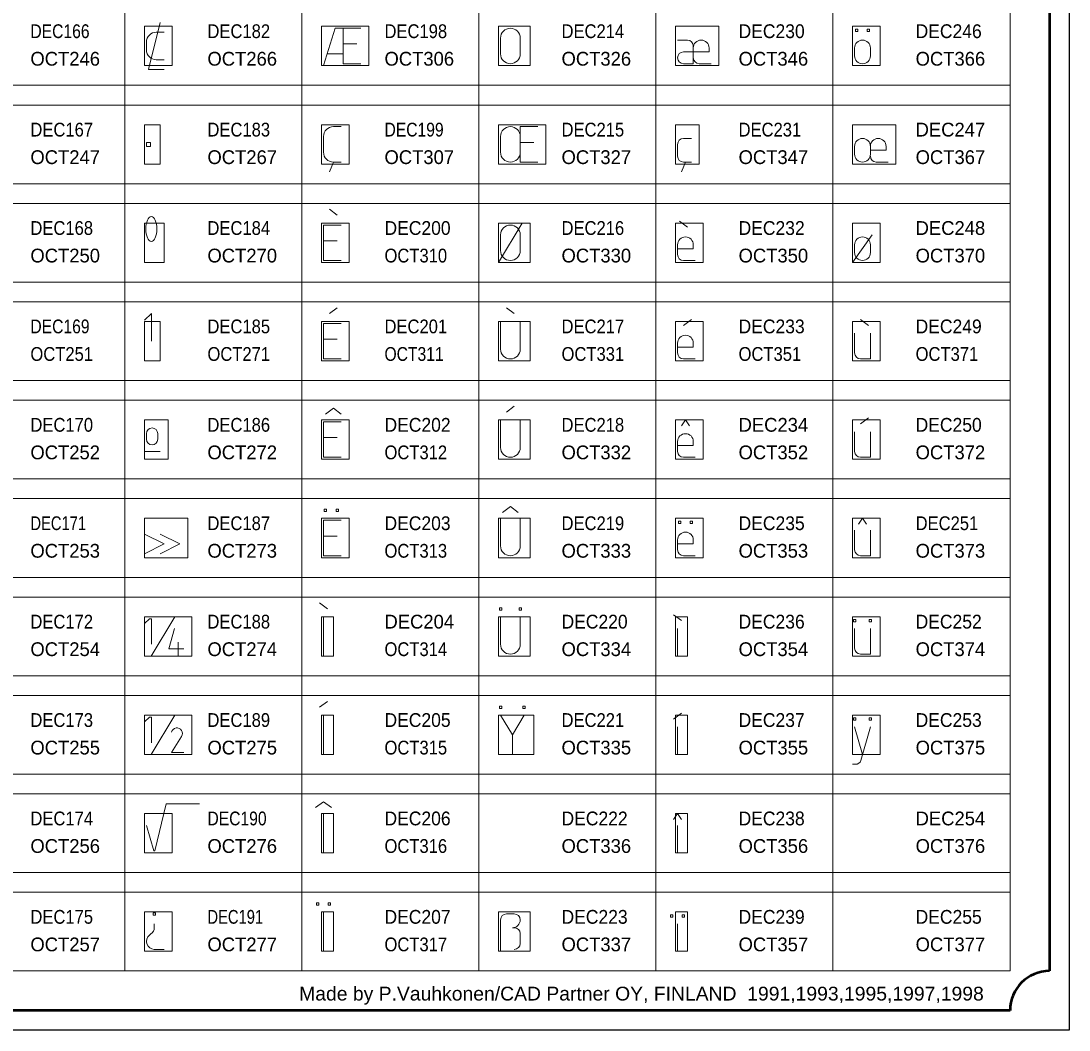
# Model space of a CAD drawing. Extents: x -200 to 7300, y -200 to 4800.
# Drawn here: x 4636 to 7300, y -200 to 2364 of the extents above; entities that cross this region are included whole.
import ezdxf
from ezdxf.enums import TextEntityAlignment as Align

# ---------------------------------------------------------------- set-up
doc = ezdxf.new("R2010")
doc.units = 0
doc.header["$LTSCALE"] = 14
for name, color, linetype, lineweight in [('1', 7, 'Continuous', 13), ('5', 7, 'Continuous', 40), ('6', 7, 'Continuous', 13), ('63', 7, 'Continuous', 13)]:
    doc.layers.add(name, color=color, linetype=linetype, lineweight=lineweight)
doc.layers.add('10', color=7, linetype='Continuous')
doc.layers.add('11', color=7, linetype='Continuous')

msp = doc.modelspace()

# ---------------------------------------------------------------- linework, layer by layer
at = {"layer": '1'}
for p, q in [((5000, 2335), (4980, 2335)), ((5855, 2320), (5855, 2280)), ((5905, 2320), (5905, 2280)), ((4955, 2310), (4955, 2290)), ((5490, 2305), (5455, 2305)), ((6305, 2315), (6330, 2315)), ((6755, 2295), (6755, 2275)), ((6795, 2295), (6795, 2275)), ((4980, 2265), (5000, 2265)), ((5414, 2280), (5455, 2280)), ((6390, 2255), (6360, 2255)), ((5450, 2095), (5430, 2095)), ((5405, 2070), (5405, 2030)), ((5855, 2070), (5855, 2030)), ((5940, 2055), (5905, 2055)), ((6340, 2065), (6320, 2065)), ((6305, 2050), (6305, 2020)), ((6755, 2045), (6755, 2025)), ((6795, 2045), (6795, 2025)), ((5430, 2005), (5420, 1980)), ((5430, 2005), (5450, 2005)), ((6325, 2005), (6315, 1980)), ((6320, 2005), (6340, 2005)), ((6840, 2005), (6810, 2005)), ((5440, 1870), (5420, 1885)), ((5850, 1750), (5910, 1850)), ((6330, 1840), (6310, 1855)), ((5855, 1820), (5855, 1780)), ((5905, 1820), (5905, 1780)), ((6800, 1820), (6750, 1750)), ((5440, 1805), (5405, 1805)), ((6305, 1770), (6305, 1795)), ((6755, 1795), (6755, 1775)), ((6795, 1795), (6795, 1775)), ((6350, 1755), (6320, 1755)), ((5420, 1620), (5440, 1635)), ((5890, 1620), (5870, 1635)), ((5855, 1600), (5855, 1530)), ((5905, 1600), (5905, 1530)), ((6320, 1590), (6340, 1605)), ((6790, 1590), (6770, 1605)), ((5440, 1555), (5405, 1555)), ((6755, 1570), (6755, 1520)), ((6305, 1520), (6305, 1545)), ((6350, 1505), (6320, 1505)), ((5870, 1370), (5890, 1385)), ((5855, 1350), (5855, 1280)), ((5905, 1350), (5905, 1280)), ((6770, 1340), (6790, 1355)), ((4955, 1315.4), (4955, 1301.1)), ((4983.6, 1315.4), (4983.6, 1301.1)), ((6755, 1320), (6755, 1270)), ((5440, 1305), (5405, 1305)), ((6305, 1270), (6305, 1295)), ((4950, 1270), (4990, 1270)), ((6350, 1255), (6320, 1255)), ((5855, 1100), (5855, 1030)), ((5905, 1100), (5905, 1030)), ((6755, 1070), (6755, 1020)), ((5440, 1055), (5405, 1055)), ((6305, 1020), (6305, 1045)), ((6350, 1005), (6320, 1005)), ((5415, 870), (5395, 885)), ((6315, 840), (6295, 855)), ((4967, 750), (5027, 850)), ((5405, 850), (5405, 750)), ((5855, 850), (5855, 780)), ((5905, 850), (5905, 780)), ((6305, 750), (6305, 820)), ((6755, 820), (6755, 770)), ((5036, 750), (5036, 785)), ((5395, 620), (5415, 635)), ((4967, 500), (5027, 600)), ((5405, 600), (5405, 500)), ((6295, 590), (6315, 605)), ((6305, 500), (6305, 570)), ((6755, 570), (6775, 500)), ((6795, 570), (6771, 485)), ((5885, 550), (5885, 500)), ((6757, 475), (6750, 475)), ((5405, 350), (5405, 250)), ((6305, 250), (6305, 320)), ((5405, 100), (5405, 0)), ((5855, 0), (5855, 80)), ((5870, 95), (5890, 95)), ((4975, 70), (4975, 61)), ((5885, 60), (5890, 60)), ((6305, 0), (6305, 70)), ((4966, 44), (4963, 41)), ((5905, 45), (5905, 20)), ((5000, 5), (4975, 5))]:
    msp.add_line(p, q, dxfattribs=at)
for points in [[(4990, 2360), (4960, 2240), (5000, 2240)], [(5405, 2250), (5435, 2345), (5500, 2345)], [(5455, 2345), (5455, 2255), (5500, 2255)], [(6345, 2300), (6345, 2255), (6320, 2255)], [(6320, 2285), (6385, 2285), (6385, 2295)], [(5950, 2095), (5905, 2095), (5905, 2005), (5950, 2005)], [(6795, 2035), (6835, 2035), (6835, 2045)], [(5450, 1845), (5405, 1845), (5405, 1755), (5450, 1755)], [(6305, 1785), (6345, 1785), (6345, 1795)], [(4968, 1550), (4968, 1620), (4950, 1603)], [(5450, 1595), (5405, 1595), (5405, 1505), (5450, 1505)], [(6770, 1505), (6795, 1505), (6795, 1570)], [(6305, 1535), (6345, 1535), (6345, 1545)], [(5450, 1365), (5430, 1380), (5410, 1365)], [(5450, 1345), (5405, 1345), (5405, 1255), (5450, 1255)], [(6335, 1335), (6325, 1350), (6315, 1335)], [(6770, 1255), (6795, 1255), (6795, 1320)], [(6305, 1285), (6345, 1285), (6345, 1295)], [(5900, 1115), (5880, 1130), (5860, 1115)], [(5450, 1095), (5405, 1095), (5405, 1005), (5450, 1005)], [(6785, 1085), (6775, 1100), (6765, 1085)], [(6770, 1005), (6795, 1005), (6795, 1070)], [(4950, 1060), (5000, 1035), (4950, 1010)], [(4990, 1060), (5040, 1035), (4990, 1010)], [(6305, 1035), (6345, 1035), (6345, 1045)], [(4968, 780), (4968, 845), (4963, 845), (4950, 833)], [(5050, 768), (5012, 768), (5026, 820)], [(6770, 755), (6795, 755), (6795, 820)], [(4968, 530), (4968, 595), (4963, 595), (4950, 583)], [(5855, 600), (5885, 550), (5915, 600)], [(5050, 505), (5019, 505), (5044.3, 545.9)], [(4955, 320), (4974, 255), (4976, 255), (5005, 375), (5090, 375)], [(5425, 365), (5405, 380), (5385, 365)], [(6315, 335), (6305, 350), (6295, 335)]]:
    msp.add_lwpolyline(points, dxfattribs=at)
for points in [[(6757, 2337), (6763, 2337), (6763, 2343), (6757, 2343)], [(6787, 2337), (6793, 2337), (6793, 2343), (6787, 2343)], [(4955, 2045), (4965, 2045), (4965, 2055), (4955, 2055)], [(5407, 1117), (5413, 1117), (5413, 1123), (5407, 1123)], [(5437, 1117), (5443, 1117), (5443, 1123), (5437, 1123)], [(6307, 1087), (6313, 1087), (6313, 1093), (6307, 1093)], [(6337, 1087), (6343, 1087), (6343, 1093), (6337, 1093)], [(5852, 867), (5858, 867), (5858, 873), (5852, 873)], [(5902, 867), (5908, 867), (5908, 873), (5902, 873)], [(6752, 837), (6758, 837), (6758, 843), (6752, 843)], [(6792, 837), (6798, 837), (6798, 843), (6792, 843)], [(5852, 617), (5858, 617), (5858, 623), (5852, 623)], [(5912, 617), (5918, 617), (5918, 623), (5912, 623)], [(6752, 587), (6758, 587), (6758, 593), (6752, 593)], [(6792, 587), (6798, 587), (6798, 593), (6792, 593)], [(5387, 117), (5393, 117), (5393, 123), (5387, 123)], [(5417, 117), (5423, 117), (5423, 123), (5417, 123)], [(4972, 92), (4978, 92), (4978, 98), (4972, 98)], [(6287, 87), (6293, 87), (6293, 93), (6287, 93)], [(6317, 87), (6323, 87), (6323, 93), (6317, 93)]]:
    msp.add_lwpolyline(points, close=True, dxfattribs=at)
for centre, radius, start, end in [((5880, 2320), 25, 0, 180), ((4980, 2310), 25, 90, 180), ((6330, 2300), 15, 0, 90), ((6365, 2295), 20, 0, 180), ((6775, 2295), 20, 0, 180), ((4980, 2290), 25, 180, 270), ((5880, 2280), 25, 180, 360), ((6320, 2270), 15, 90, 270), ((6360, 2270), 15, 180, 270), ((6775, 2275), 20, 180, 360), ((5430, 2070), 25, 90, 180), ((5880, 2070), 25, 0, 180), ((6320, 2050), 15, 90, 180), ((6775, 2045), 20, 0, 180), ((6815, 2045), 20, 0, 180), ((5430, 2030), 25, 180, 270), ((5880, 2030), 25, 180, 360), ((6775, 2025), 20, 180, 360), ((6320, 2020), 15, 180, 270), ((6810, 2020), 15, 180, 270), ((5880, 1820), 25, 0, 180), ((6325, 1795), 20, 0, 180), ((6775, 1795), 20, 0, 180), ((5880, 1780), 25, 180, 360), ((6320, 1770), 15, 180, 270), ((6775, 1775), 20, 180, 360), ((6325, 1545), 20, 0, 180), ((5880, 1530), 25, 180, 360), ((6320, 1520), 15, 180, 270), ((6770, 1520), 15, 180, 270), ((4969.3, 1315.4), 14.3, 0, 180), ((6325, 1295), 20, 0, 180), ((4969.3, 1301.1), 14.3, 180, 360), ((5880, 1280), 25, 180, 360), ((6320, 1270), 15, 180, 270), ((6770, 1270), 15, 180, 270), ((6325, 1045), 20, 0, 180), ((5880, 1030), 25, 180, 360), ((6320, 1020), 15, 180, 270), ((6770, 1020), 15, 180, 270), ((5880, 780), 25, 180, 360), ((6770, 770), 15, 180, 270), ((5032.5, 553.5), 14, 327.0948, 165.9638), ((6757.1, 490), 15, 270, 338.5769), ((5870, 80), 15, 90, 180), ((5885, 80), 20, 270, 360), ((5890, 80), 15, 0, 90), ((4955, 60.7), 20, 303.6901, 360), ((5890, 45), 15, 0, 90), ((4975, 25), 20, 126.8699, 270), ((5890, 20), 15, 270, 0)]:
    msp.add_arc(centre, radius, start, end, dxfattribs=at)
msp.add_ellipse((4967.5, 1835), major_axis=(0, -31.5), ratio=0.444444, dxfattribs=at)
at = {"layer": '5', "lineweight": 53}
for p, q in [((7250, 4650), (7250, -50)), ((7150, -150), (-50, -150))]:
    msp.add_line(p, q, dxfattribs=at)
at = {"layer": '5', "lineweight": 25}
msp.add_lwpolyline([(-200, -200), (-200, 4800), (7300, 4800), (7300, -200)], close=True, dxfattribs=at)
at = {"layer": '5', "lineweight": 53}
msp.add_arc((7250, -150), 100, 90, 180, dxfattribs=at)
at = {"layer": '6'}
for p, q in [((4900, 3950), (4900, -50)), ((5350, 3950), (5350, -50)), ((5800, 3950), (5800, -50)), ((6250, 3950), (6250, -50)), ((6700, 3950), (6700, -50)), ((7150, 3950), (7150, -50)), ((-50, 2200), (7150, 2200)), ((-50, 2150), (7150, 2150)), ((-50, 1950), (7150, 1950)), ((-50, 1900), (7150, 1900)), ((-50, 1700), (7150, 1700)), ((-50, 1650), (7150, 1650)), ((-50, 1450), (7150, 1450)), ((-50, 1400), (7150, 1400)), ((-50, 1200), (7150, 1200)), ((-50, 1150), (7150, 1150)), ((-50, 950), (7150, 950)), ((-50, 900), (7150, 900)), ((-50, 700), (7150, 700)), ((-50, 650), (7150, 650)), ((-50, 450), (7150, 450)), ((-50, 400), (7150, 400)), ((-50, 200), (7150, 200)), ((-50, 150), (7150, 150)), ((-50, -50), (7150, -50))]:
    msp.add_line(p, q, dxfattribs=at)
at = {"layer": '63'}
for points in [[(4950, 2250), (5020, 2250), (5020, 2350), (4950, 2350)], [(5400, 2250), (5520, 2250), (5520, 2350), (5400, 2350)], [(5850, 2250), (5930, 2250), (5930, 2350), (5850, 2350)], [(6300, 2250), (6410, 2250), (6410, 2350), (6300, 2350)], [(6750, 2250), (6820, 2250), (6820, 2350), (6750, 2350)], [(4950, 2000), (4990, 2000), (4990, 2100), (4950, 2100)], [(5400, 2000), (5470, 2000), (5470, 2100), (5400, 2100)], [(5850, 2000), (5970, 2000), (5970, 2100), (5850, 2100)], [(6300, 2000), (6360, 2000), (6360, 2100), (6300, 2100)], [(6750, 2000), (6860, 2000), (6860, 2100), (6750, 2100)], [(4950, 1750), (5000, 1750), (5000, 1850), (4950, 1850)], [(5400, 1750), (5470, 1750), (5470, 1850), (5400, 1850)], [(5850, 1750), (5930, 1750), (5930, 1850), (5850, 1850)], [(6300, 1750), (6370, 1750), (6370, 1850), (6300, 1850)], [(6750, 1750), (6820, 1750), (6820, 1850), (6750, 1850)], [(4950, 1500), (4990, 1500), (4990, 1600), (4950, 1600)], [(5400, 1500), (5470, 1500), (5470, 1600), (5400, 1600)], [(5850, 1500), (5930, 1500), (5930, 1600), (5850, 1600)], [(6300, 1500), (6370, 1500), (6370, 1600), (6300, 1600)], [(6750, 1500), (6820, 1500), (6820, 1600), (6750, 1600)], [(4950, 1250), (5010, 1250), (5010, 1350), (4950, 1350)], [(5400, 1250), (5470, 1250), (5470, 1350), (5400, 1350)], [(5850, 1250), (5930, 1250), (5930, 1350), (5850, 1350)], [(6300, 1250), (6370, 1250), (6370, 1350), (6300, 1350)], [(6750, 1250), (6820, 1250), (6820, 1350), (6750, 1350)], [(4950, 1000), (5060, 1000), (5060, 1100), (4950, 1100)], [(5400, 1000), (5470, 1000), (5470, 1100), (5400, 1100)], [(5850, 1000), (5930, 1000), (5930, 1100), (5850, 1100)], [(6300, 1000), (6370, 1000), (6370, 1100), (6300, 1100)], [(6750, 1000), (6820, 1000), (6820, 1100), (6750, 1100)], [(4950, 750), (5070, 750), (5070, 850), (4950, 850)], [(5400, 750), (5430, 750), (5430, 850), (5400, 850)], [(5850, 750), (5930, 750), (5930, 850), (5850, 850)], [(6300, 750), (6330, 750), (6330, 850), (6300, 850)], [(6750, 750), (6820, 750), (6820, 850), (6750, 850)], [(4950, 500), (5070, 500), (5070, 600), (4950, 600)], [(5400, 500), (5430, 500), (5430, 600), (5400, 600)], [(5850, 500), (5940, 500), (5940, 600), (5850, 600)], [(6300, 500), (6330, 500), (6330, 600), (6300, 600)], [(6750, 500), (6820, 500), (6820, 600), (6750, 600)], [(4950, 250), (5020, 250), (5020, 350), (4950, 350)], [(5400, 250), (5430, 250), (5430, 350), (5400, 350)], [(6300, 250), (6330, 250), (6330, 350), (6300, 350)], [(4950, 100), (5020, 100), (5020, 0), (4950, 0)], [(5400, 0), (5430, 0), (5430, 100), (5400, 100)], [(5850, 0), (5930, 0), (5930, 100), (5850, 100)], [(6300, 0), (6330, 0), (6330, 100), (6300, 100)]]:
    msp.add_lwpolyline(points, close=True, dxfattribs=at)

# ---------------------------------------------------------------- texts
at = {"layer": '10'}
for s, width, p in [('DEC166', 0.85, (4660, 2320)), ('DEC182', 0.9, (5110, 2320)), ('DEC198', 0.9, (5560, 2320)), ('DEC214', 0.9, (6010, 2320)), ('DEC230', 0.95, (6460, 2320)), ('DEC246', 0.95, (6910, 2320)), ('DEC167', 0.9, (4660, 2070)), ('DEC183', 0.9, (5110, 2070)), ('DEC199', 0.85, (5560, 2070)), ('DEC215', 0.9, (6010, 2070)), ('DEC231', 0.9, (6460, 2070)), ('DEC168', 0.9, (4660, 1820)), ('DEC184', 0.9, (5110, 1820)), ('DEC200', 0.95, (5560, 1820)), ('DEC216', 0.9, (6010, 1820)), ('DEC232', 0.95, (6460, 1820)), ('DEC169', 0.85, (4660, 1570)), ('DEC185', 0.9, (5110, 1570)), ('DEC201', 0.9, (5560, 1570)), ('DEC217', 0.9, (6010, 1570)), ('DEC233', 0.95, (6460, 1570)), ('DEC249', 0.95, (6910, 1570)), ('DEC170', 0.9, (4660, 1320)), ('DEC186', 0.9, (5110, 1320)), ('DEC202', 0.95, (5560, 1320)), ('DEC218', 0.9, (6010, 1320)), ('DEC250', 0.95, (6910, 1320)), ('DEC171', 0.8, (4660, 1070)), ('DEC187', 0.9, (5110, 1070)), ('DEC203', 0.95, (5560, 1070)), ('DEC219', 0.9, (6010, 1070)), ('DEC235', 0.95, (6460, 1070)), ('DEC251', 0.9, (6910, 1070)), ('DEC172', 0.9, (4660, 820)), ('DEC188', 0.9, (5110, 820)), ('DEC220', 0.95, (6010, 820)), ('DEC236', 0.95, (6460, 820)), ('DEC252', 0.95, (6910, 820)), ('DEC173', 0.9, (4660, 570)), ('DEC189', 0.9, (5110, 570)), ('DEC205', 0.95, (5560, 570)), ('DEC221', 0.9, (6010, 570)), ('DEC237', 0.95, (6460, 570)), ('DEC253', 0.95, (6910, 570)), ('DEC174', 0.9, (4660, 320)), ('DEC190', 0.85, (5110, 320)), ('DEC206', 0.95, (5560, 320)), ('DEC222', 0.95, (6010, 320)), ('DEC238', 0.95, (6460, 320)), ('DEC175', 0.9, (4660, 70)), ('DEC191', 0.8, (5110, 70)), ('DEC207', 0.95, (5560, 70)), ('DEC223', 0.95, (6010, 70)), ('DEC239', 0.95, (6460, 70)), ('DEC255', 0.95, (6910, 70))]:
    msp.add_text(s, height=35, dxfattribs=dict(at, width=width)).set_placement(p)
for s, p in [('DEC247', (6910, 2070)), ('DEC248', (6910, 1820)), ('DEC234', (6460, 1320)), ('DEC204', (5560, 820)), ('DEC254', (6910, 320))]:
    msp.add_text(s, height=35, dxfattribs=at).set_placement(p)
at = {"layer": '11'}
for s, p in [('OCT246', (4660, 2250)), ('OCT266', (5110, 2250)), ('OCT306', (5560, 2250)), ('OCT326', (6010, 2250)), ('OCT346', (6460, 2250)), ('OCT366', (6910, 2250)), ('OCT247', (4660, 2000)), ('OCT267', (5110, 2000)), ('OCT307', (5560, 2000)), ('OCT327', (6010, 2000)), ('OCT347', (6460, 2000)), ('OCT367', (6910, 2000)), ('OCT250', (4660, 1750)), ('OCT270', (5110, 1750)), ('OCT330', (6010, 1750)), ('OCT350', (6460, 1750)), ('OCT370', (6910, 1750)), ('OCT252', (4660, 1250)), ('OCT272', (5110, 1250)), ('OCT332', (6010, 1250)), ('OCT352', (6460, 1250)), ('OCT372', (6910, 1250)), ('OCT253', (4660, 1000)), ('OCT273', (5110, 1000)), ('OCT333', (6010, 1000)), ('OCT353', (6460, 1000)), ('OCT373', (6910, 1000)), ('OCT254', (4660, 750)), ('OCT274', (5110, 750)), ('OCT334', (6010, 750)), ('OCT354', (6460, 750)), ('OCT374', (6910, 750)), ('OCT255', (4660, 500)), ('OCT275', (5110, 500)), ('OCT335', (6010, 500)), ('OCT355', (6460, 500)), ('OCT375', (6910, 500)), ('OCT256', (4660, 250)), ('OCT276', (5110, 250)), ('OCT336', (6010, 250)), ('OCT356', (6460, 250)), ('OCT376', (6910, 250)), ('OCT257', (4660, 0)), ('OCT277', (5110, 0)), ('OCT337', (6010, 0)), ('OCT357', (6460, 0)), ('OCT377', (6910, 0))]:
    msp.add_text(s, height=35, dxfattribs=at).set_placement(p)
for s, width, p in [('OCT310', 0.9, (5560, 1750)), ('OCT251', 0.9, (4660, 1500)), ('OCT271', 0.9, (5110, 1500)), ('OCT311', 0.85, (5560, 1500)), ('OCT331', 0.9, (6010, 1500)), ('OCT351', 0.9, (6460, 1500)), ('OCT371', 0.9, (6910, 1500)), ('OCT312', 0.9, (5560, 1250)), ('OCT313', 0.9, (5560, 1000)), ('OCT314', 0.9, (5560, 750)), ('OCT315', 0.9, (5560, 500)), ('OCT316', 0.9, (5560, 250)), ('OCT317', 0.9, (5560, 0))]:
    msp.add_text(s, height=35, dxfattribs=dict(at, width=width)).set_placement(p)
at = {"layer": '5', "width": 1.05}
msp.add_text('Made by P.Vauhkonen/CAD Partner OY, FINLAND  1991,1993,1995,1997,1998', height=35, dxfattribs=at).set_placement((7083.3, -125), align=Align.RIGHT)

doc.saveas('drawing.dxf')
